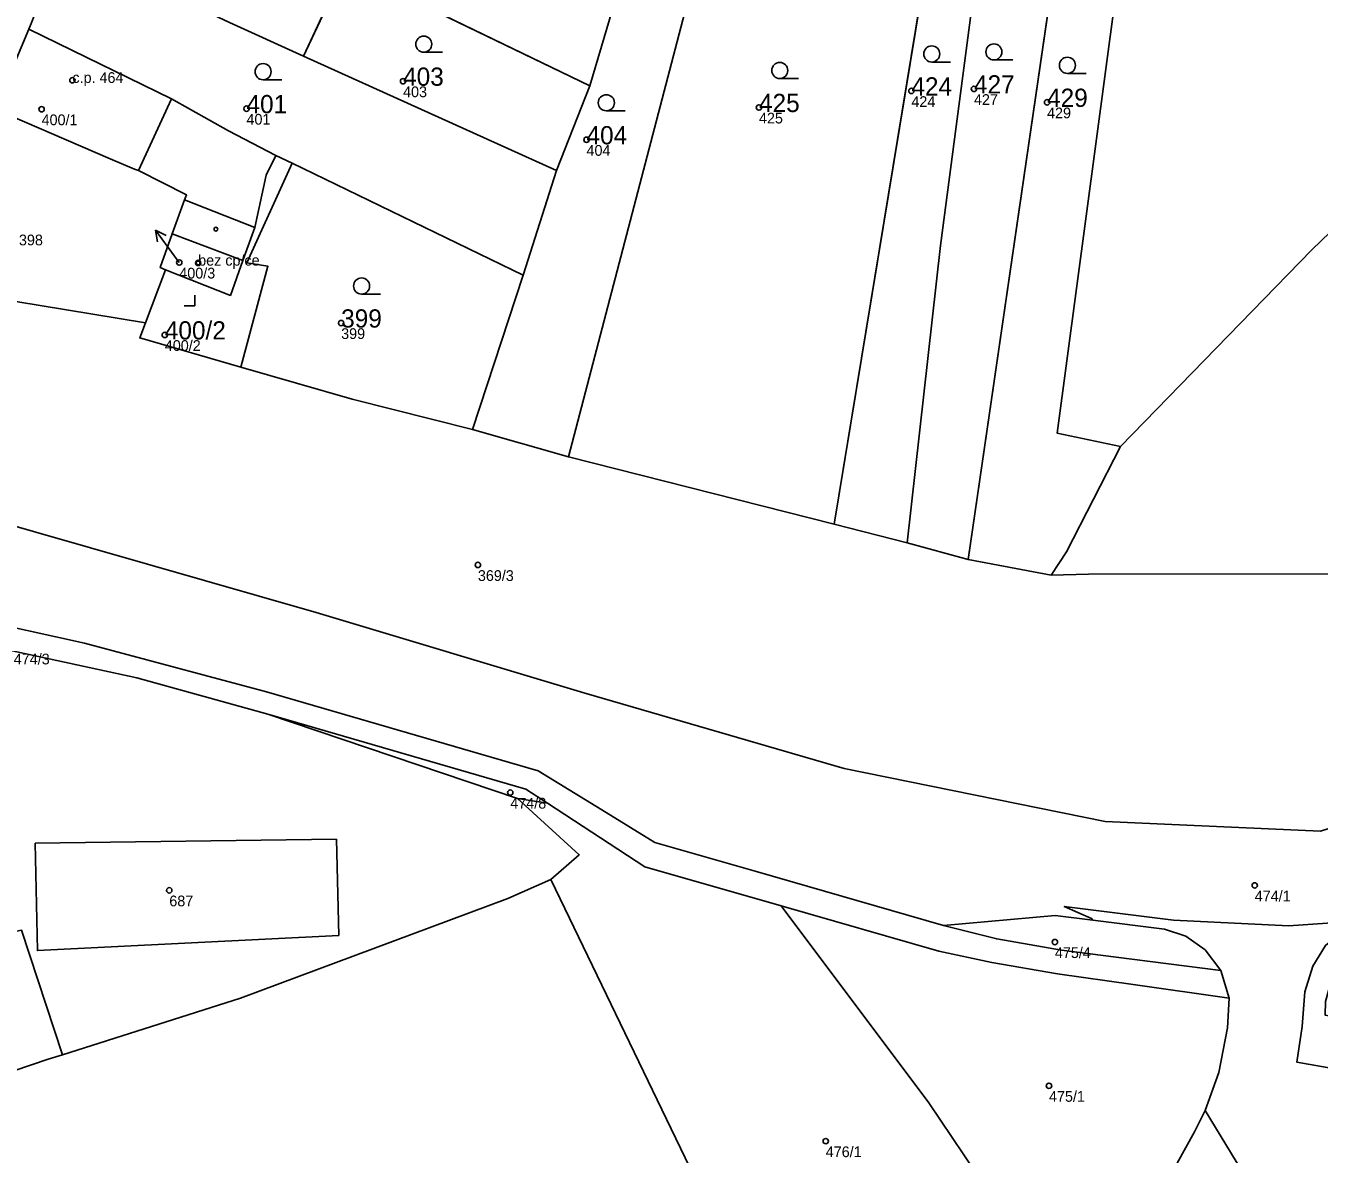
# Model space of a CAD drawing. Extents: x -878211 to -870363, y -1058464 to -1052522.
# Drawn here: x -874484.1 to -874363.6, y -1056425.6 to -1056320.4 of the extents above; entities that cross this region are included whole.
import ezdxf

# ---------------------------------------------------------------- set-up
doc = ezdxf.new("R2010")
doc.units = 0
for name, color, linetype in [('Vrstva 1', 7, 'Continuous'), ('Vrstva 2', 7, 'Continuous'), ('Vrstva 3', 7, 'Continuous'), ('Vrstva 4', 7, 'Continuous'), ('Vrstva 5', 7, 'Continuous'), ('Vrstva 50', 7, 'Continuous'), ('Vrstva 51', 7, 'Continuous'), ('Vrstva 52', 7, 'Continuous'), ('Vrstva 7', 7, 'Continuous')]:
    doc.layers.add(name, color=color, linetype=linetype)

msp = doc.modelspace()

# ---------------------------------------------------------------- linework, layer by layer
at = {"layer": 'Vrstva 1'}
for p, q in [((-874394.05, -1056277.02), (-874408.81, -1056366.88)), ((-874396.34, -1056370.15), (-874384.87, -1056291.52)), ((-874458.27, -1056323.23), (-874454.4, -1056314.98)), ((-874431.59, -1056326), (-874454.4, -1056314.98)), ((-874434.69, -1056333.9), (-874458.27, -1056323.23)), ((-874434.69, -1056333.9), (-874431.59, -1056326)), ((-874459.33, -1056333.22), (-874460.83, -1056332.49)), ((-874437.8, -1056343.65), (-874459.33, -1056333.22)), ((-874437.8, -1056343.65), (-874434.69, -1056333.9)), ((-874470.49, -1056339.81), (-874463.91, -1056342.3)), ((-874473, -1056348.11), (-874471.14, -1056343.15)), ((-874442.52, -1056358.05), (-874437.8, -1056343.65)), ((-874473.53, -1056349.51), (-874464.1, -1056352.23)), ((-874464.1, -1056352.23), (-874453.72, -1056355.22)), ((-874453.72, -1056355.22), (-874442.52, -1056358.05)), ((-874433.58, -1056360.58), (-874442.52, -1056358.05)), ((-874433.58, -1056360.58), (-874408.81, -1056366.88))]:
    msp.add_line(p, q, dxfattribs=at)
for points in [[(-874417.27, -1056285.77), (-874419.76, -1056303.99), (-874420.48, -1056308.81), (-874422.58, -1056318.54), (-874433.58, -1056360.58)], [(-874402.03, -1056368.61), (-874398.91, -1056340.89), (-874395.91, -1056317.97), (-874390.55, -1056288.09)], [(-874382.15, -1056359.62), (-874388.04, -1056358.4), (-874382.65, -1056317.89), (-874379.48, -1056292.14)], [(-874428.05, -1056309.75), (-874428.16, -1056314.44), (-874431.59, -1056326)], [(-874388.61, -1056371.61), (-874385.14, -1056371.54), (-874356.24, -1056371.49), (-874347.06, -1056367.91), (-874344.01, -1056366.72), (-874341.65, -1056364.53), (-874305.59, -1056328.15), (-874284.45, -1056312)], [(-874458.27, -1056323.23), (-874465.16, -1056320.12), (-874480.74, -1056312.73)], [(-874460.83, -1056332.49), (-874465.27, -1056330.21), (-874470.58, -1056327.23), (-874483.86, -1056320.72)], [(-874470.49, -1056339.81), (-874469.35, -1056336.63), (-874469.17, -1056336.17), (-874473.64, -1056333.91), (-874474.02, -1056333.77), (-874476.28, -1056332.82), (-874487.02, -1056328.19)], [(-874348.41, -1056328.4), (-874349.53, -1056329.25), (-874357.55, -1056334.76), (-874364.33, -1056341.31), (-874382.15, -1056359.62)], [(-874460.83, -1056332.49), (-874461.75, -1056334.33), (-874462.81, -1056339.21), (-874463.91, -1056342.3)], [(-874459.33, -1056333.22), (-874463.54, -1056342.5), (-874461.59, -1056342.82), (-874464.1, -1056352.23)], [(-874471.14, -1056343.15), (-874471.62, -1056342.95), (-874470.49, -1056339.81)], [(-874463.91, -1056342.3), (-874465.07, -1056345.54), (-874471.14, -1056343.15)], [(-874388.61, -1056371.61), (-874387.19, -1056369.44), (-874382.15, -1056359.62)]]:
    msp.add_lwpolyline(points, dxfattribs=at)
at = {"layer": 'Vrstva 3'}
for p, q in [((-874447.063, -1056322.88), (-874445.313, -1056322.88)), ((-874399.733, -1056323.79), (-874397.983, -1056323.79)), ((-874393.943, -1056323.6), (-874392.193, -1056323.6)), ((-874462.033, -1056325.44), (-874460.283, -1056325.44)), ((-874413.893, -1056325.33), (-874412.143, -1056325.33)), ((-874387.093, -1056324.85), (-874385.343, -1056324.85)), ((-874430.053, -1056328.34), (-874428.303, -1056328.34)), ((-874468.4, -1056346.52), (-874468.4, -1056345.52)), ((-874452.853, -1056345.42), (-874451.103, -1056345.42)), ((-874469.401, -1056346.52), (-874468.4, -1056346.52))]:
    msp.add_line(p, q, dxfattribs=at)
for centre in [(-874447.06286, -1056322.12981), (-874399.73286, -1056323.03981), (-874393.94286, -1056322.84981), (-874462.03286, -1056324.68981), (-874413.89286, -1056324.57981), (-874387.09286, -1056324.09981), (-874430.05286, -1056327.58981), (-874452.85286, -1056344.66981)]:
    msp.add_circle(centre, 0.75, dxfattribs=at)
at = {"layer": 'Vrstva 4'}
for p, q in [((-874473.64, -1056333.91), (-874470.58, -1056327.23)), ((-874469.35, -1056336.63), (-874462.81, -1056339.21))]:
    msp.add_line(p, q, dxfattribs=at)
at = {"layer": 'Vrstva 5'}
for centre in [(-874466.4268, -1056339.36916), (-874468.0868, -1056342.51916)]:
    msp.add_circle(centre, 0.175, dxfattribs=at)
at = {"layer": 'Vrstva 50'}
for centre in [(-874479.8, -1056325.48994), (-874448.99, -1056325.57994), (-874401.63, -1056326.48994), (-874395.8, -1056326.29994), (-874415.83, -1056328.02994), (-874388.99, -1056327.54994), (-874482.67, -1056328.18994), (-874463.58, -1056328.13994), (-874431.9, -1056331.03994), (-874469.84, -1056342.47994), (-874468.08, -1056342.51994), (-874454.76, -1056348.11994), (-874471.19, -1056349.22994), (-874442.02, -1056370.66994), (-874439, -1056391.88994), (-874470.77, -1056400.99994), (-874369.64, -1056400.53994), (-874388.26, -1056405.81994), (-874388.81, -1056419.21994), (-874409.61, -1056424.37994)]:
    msp.add_circle(centre, 0.25, dxfattribs=at)
at = {"layer": 'Vrstva 51'}
for points in [[(-874408.81, -1056366.88), (-874394.05, -1056277.02), (-874401.74, -1056275.56), (-874403.83, -1056275.64), (-874403.83, -1056277.39), (-874403.02, -1056283.55), (-874406.67, -1056284.12), (-874410.17, -1056284.66), (-874413.67, -1056285.21), (-874416.82, -1056285.7), (-874417.27, -1056285.77), (-874419.76, -1056303.99), (-874420.48, -1056308.81), (-874422.58, -1056318.54), (-874433.58, -1056360.58)], [(-874402.03, -1056368.61), (-874398.91, -1056340.89), (-874395.91, -1056317.97), (-874390.55, -1056288.09), (-874389.52, -1056277.88), (-874394.05, -1056277.02), (-874408.81, -1056366.88)], [(-874396.34, -1056370.15), (-874384.87, -1056291.52), (-874382.69, -1056279.17), (-874389.52, -1056277.88), (-874390.55, -1056288.09), (-874395.91, -1056317.97), (-874398.91, -1056340.89), (-874402.03, -1056368.61)], [(-874388.61, -1056371.61), (-874387.19, -1056369.44), (-874382.15, -1056359.62), (-874388.04, -1056358.4), (-874382.65, -1056317.89), (-874379.48, -1056292.14), (-874378.04, -1056280.05), (-874382.69, -1056279.17), (-874384.87, -1056291.52), (-874396.34, -1056370.15)], [(-874428.05, -1056309.75), (-874428.16, -1056314.44), (-874431.59, -1056326), (-874434.69, -1056333.9), (-874437.8, -1056343.65), (-874442.52, -1056358.05), (-874433.58, -1056360.58), (-874422.58, -1056318.54), (-874420.48, -1056308.81), (-874419.76, -1056303.99), (-874417.27, -1056285.77), (-874420.36, -1056286.3), (-874424.05, -1056286.92), (-874427.89, -1056287.57), (-874431.19, -1056288.13), (-874432.46, -1056288.35), (-874430.92, -1056292.23), (-874429.1, -1056294.96), (-874425.54, -1056295.23), (-874426.84, -1056310.1)], [(-874428.05, -1056309.75), (-874445.92, -1056303.86), (-874449.03, -1056302.71), (-874453.23, -1056312.49), (-874454.4, -1056314.98), (-874431.59, -1056326), (-874428.16, -1056314.44)], [(-874462.69, -1056311.5), (-874462.85, -1056311.43), (-874476.21, -1056304.64), (-874480.74, -1056312.73), (-874465.16, -1056320.12), (-874458.27, -1056323.23), (-874454.4, -1056314.98), (-874460.07, -1056312.6)], [(-874305.59, -1056328.15), (-874284.45, -1056312), (-874285.09, -1056309.2), (-874306.98, -1056315.64), (-874311.81, -1056317.09), (-874332.51, -1056323.25), (-874331.57, -1056326.4), (-874336.9, -1056327.87), (-874347.73, -1056330.86), (-874348.41, -1056328.4), (-874349.53, -1056329.25), (-874357.55, -1056334.76), (-874364.33, -1056341.31), (-874382.15, -1056359.62), (-874387.19, -1056369.44), (-874388.61, -1056371.61), (-874385.14, -1056371.54), (-874356.24, -1056371.49), (-874347.06, -1056367.91), (-874344.01, -1056366.72), (-874341.65, -1056364.53)], [(-874434.69, -1056333.9), (-874458.27, -1056323.23), (-874465.16, -1056320.12), (-874480.74, -1056312.73), (-874483.57, -1056320.05), (-874483.86, -1056320.72), (-874470.58, -1056327.23), (-874465.27, -1056330.21), (-874460.83, -1056332.49), (-874459.33, -1056333.22), (-874437.8, -1056343.65)], [(-874431.59, -1056326), (-874454.4, -1056314.98), (-874458.27, -1056323.23), (-874434.69, -1056333.9)], [(-874470.49, -1056339.81), (-874463.91, -1056342.3), (-874462.81, -1056339.21), (-874461.75, -1056334.33), (-874460.83, -1056332.49), (-874465.27, -1056330.21), (-874470.58, -1056327.23), (-874483.86, -1056320.72), (-874486.75, -1056327.55), (-874487.02, -1056328.19), (-874476.28, -1056332.82), (-874474.02, -1056333.77), (-874473.64, -1056333.91), (-874469.17, -1056336.17), (-874469.35, -1056336.63)], [(-874473, -1056348.11), (-874471.14, -1056343.15), (-874471.62, -1056342.95), (-874470.49, -1056339.81), (-874469.35, -1056336.63), (-874469.17, -1056336.17), (-874473.64, -1056333.91), (-874474.02, -1056333.77), (-874476.28, -1056332.82), (-874487.02, -1056328.19), (-874487.42, -1056329.42), (-874492.46, -1056344.89)], [(-874464.1, -1056352.23), (-874461.59, -1056342.82), (-874463.54, -1056342.5), (-874459.33, -1056333.22), (-874460.83, -1056332.49), (-874461.75, -1056334.33), (-874462.81, -1056339.21), (-874463.91, -1056342.3), (-874465.07, -1056345.54), (-874471.14, -1056343.15), (-874473, -1056348.11), (-874473.53, -1056349.51)], [(-874453.72, -1056355.22), (-874442.52, -1056358.05), (-874437.8, -1056343.65), (-874459.33, -1056333.22), (-874463.54, -1056342.5), (-874461.59, -1056342.82), (-874464.1, -1056352.23)], [(-874471.14, -1056343.15), (-874465.07, -1056345.54), (-874463.91, -1056342.3), (-874470.49, -1056339.81), (-874471.62, -1056342.95)], [(-874480.73, -1056416.32), (-874464.13, -1056411.06), (-874439.22, -1056401.77), (-874435.23, -1056399.98), (-874432.58, -1056397.69), (-874438.32, -1056392.45), (-874461.59, -1056384.57), (-874473.8, -1056381.18), (-874495.04, -1056376.59), (-874496.42, -1056387.17), (-874497.18, -1056388.52), (-874500.89, -1056392.21), (-874504.25, -1056392.93), (-874510.08, -1056393.87), (-874552.37, -1056396.35), (-874577.98, -1056401.51), (-874580.53, -1056402.03), (-874578.38, -1056409.61), (-874573.13, -1056410.85), (-874572.76, -1056413.05), (-874571.8, -1056418.71), (-874544.06, -1056414.29), (-874506.28, -1056409.52), (-874484.53, -1056404.72)], [(-874438.32, -1056392.45), (-874435.53, -1056392.89), (-874437.55, -1056391.57), (-874461.59, -1056384.57)], [(-874361.01, -1056406.98), (-874359.27, -1056405.94), (-874352.93, -1056404.59), (-874347.41, -1056403.07), (-874318.59, -1056393.97), (-874317.8, -1056395.68), (-874314.94, -1056394.5), (-874315.68, -1056390.9), (-874347.93, -1056401.08), (-874353.93, -1056402.7), (-874359.31, -1056403.8), (-874360.99, -1056404.48), (-874363.04, -1056406.14), (-874364.23, -1056408.07), (-874364.97, -1056410.45), (-874365.23, -1056413.7), (-874365.71, -1056417.03), (-874353.17, -1056419.23), (-874351.21, -1056414.7), (-874363.09, -1056412.62), (-874363.04, -1056411.36), (-874362.3, -1056408.69)], [(-874455.2, -1056396.23), (-874454.98, -1056405.2), (-874483.06, -1056406.62), (-874483.26, -1056396.61)], [(-874455.2, -1056396.23), (-874483.26, -1056396.61), (-874483.06, -1056406.62), (-874454.98, -1056405.2)], [(-874480.73, -1056416.32), (-874482.07, -1056416.75), (-874490.03, -1056419.45), (-874505.5, -1056424.13), (-874506.63, -1056424.46), (-874506.09, -1056462.44), (-874483.53, -1056458.93), (-874476.75, -1056456.82), (-874458.26, -1056450.98), (-874448.21, -1056442.41), (-874441.44, -1056436.86), (-874425.29, -1056433.14), (-874420.12, -1056431.27), (-874435.23, -1056399.98), (-874439.22, -1056401.77), (-874464.13, -1056411.06)], [(-874413.76, -1056402.45), (-874399.99, -1056420.8), (-874384.79, -1056443.42), (-874382.93, -1056444.85), (-874382.6, -1056441.37), (-874382, -1056437.94), (-874381.27, -1056435.06), (-874380.43, -1056433.22), (-874379.13, -1056430.54), (-874375.26, -1056423.52), (-874374.27, -1056421.51), (-874373, -1056417.98), (-874372.17, -1056413.82), (-874372.03, -1056411.06), (-874380.96, -1056409.78), (-874388.01, -1056408.78), (-874394.12, -1056407.72), (-874399.07, -1056406.68)], [(-874372.79, -1056408.47), (-874374.26, -1056406.56), (-874376.05, -1056405.28), (-874378.06, -1056404.61), (-874384.74, -1056403.78), (-874388.24, -1056403.34), (-874398.64, -1056404.27), (-874393.67, -1056405.53), (-874387.64, -1056406.59), (-874382.56, -1056407.24)], [(-874506.63, -1056424.46), (-874505.5, -1056424.13), (-874490.03, -1056419.45), (-874482.07, -1056416.75), (-874480.73, -1056416.32), (-874484.53, -1056404.72), (-874506.28, -1056409.52), (-874544.06, -1056414.29), (-874571.8, -1056418.71), (-874569.39, -1056432.89), (-874561.56, -1056432.43), (-874554.89, -1056431.78), (-874547.93, -1056431.29), (-874538.64, -1056430.41), (-874535.46, -1056430.33), (-874523.03, -1056429.03), (-874509.91, -1056425.43)]]:
    msp.add_lwpolyline(points, close=True, dxfattribs=at)
for points in [[(-874486.75, -1056327.55), (-874483.86, -1056320.72), (-874483.57, -1056320.05), (-874480.74, -1056312.73), (-874476.21, -1056304.64), (-874473.19, -1056299.28), (-874471.52, -1056296.81), (-874469.69, -1056293.7), (-874480.72, -1056293.66), (-874486.23, -1056307.5)], [(-874284.45, -1056312), (-874305.59, -1056328.15), (-874341.65, -1056364.53), (-874344.01, -1056366.72), (-874347.06, -1056367.91), (-874356.24, -1056371.49), (-874385.14, -1056371.54), (-874388.61, -1056371.61), (-874396.34, -1056370.15), (-874402.03, -1056368.61), (-874408.81, -1056366.88), (-874433.58, -1056360.58), (-874442.52, -1056358.05), (-874453.72, -1056355.22), (-874464.1, -1056352.23), (-874473.53, -1056349.51), (-874473, -1056348.11), (-874492.46, -1056344.89)], [(-874382.65, -1056317.89), (-874388.04, -1056358.4), (-874382.15, -1056359.62), (-874364.33, -1056341.31), (-874357.55, -1056334.76), (-874349.53, -1056329.25), (-874348.41, -1056328.4), (-874337.74, -1056324.81), (-874332.51, -1056323.25), (-874311.81, -1056317.09)], [(-874488.56, -1056366.09), (-874457.08, -1056375.11), (-874432.15, -1056382.58), (-874407.9, -1056389.64), (-874383.57, -1056394.58), (-874363.5, -1056395.5), (-874329.41, -1056384.68), (-874311.2, -1056368.22), (-874284.49, -1056339.46), (-874263.34, -1056326.47), (-874262.52, -1056328.77), (-874260.4, -1056327.93), (-874261.1, -1056326.28), (-874247.93, -1056324.46), (-874211.49, -1056322.17)], [(-874205.44, -1056365.67), (-874230.66, -1056368.26), (-874238.99, -1056368.29), (-874258.43, -1056369.19), (-874280.88, -1056373.67), (-874329.41, -1056384.68), (-874363.5, -1056395.5), (-874383.57, -1056394.58), (-874407.9, -1056389.64), (-874432.15, -1056382.58), (-874457.08, -1056375.11), (-874488.56, -1056366.09)], [(-874495.04, -1056376.59), (-874473.8, -1056381.18), (-874461.59, -1056384.57), (-874437.55, -1056391.57), (-874435.53, -1056392.89), (-874426.47, -1056398.8), (-874413.76, -1056402.45), (-874399.07, -1056406.68), (-874394.12, -1056407.72), (-874388.01, -1056408.78), (-874380.96, -1056409.78), (-874372.03, -1056411.06), (-874372.79, -1056408.47), (-874382.56, -1056407.24), (-874387.64, -1056406.59), (-874393.67, -1056405.53), (-874398.64, -1056404.27), (-874416.2, -1056399.21), (-874425.52, -1056396.53), (-874430.06, -1056393.75), (-874436.39, -1056389.87), (-874461.71, -1056382.51), (-874478.68, -1056377.96), (-874492.07, -1056375.02)], [(-874492.07, -1056375.02), (-874478.68, -1056377.96), (-874461.71, -1056382.51), (-874436.39, -1056389.87), (-874430.06, -1056393.75), (-874425.52, -1056396.53), (-874416.2, -1056399.21), (-874398.64, -1056404.27), (-874388.24, -1056403.34), (-874384.74, -1056403.78), (-874384.84, -1056403.62), (-874387.39, -1056402.52), (-874377.2, -1056403.78), (-874366.46, -1056404.32), (-874359.31, -1056403.8)], [(-874384.79, -1056443.42), (-874399.99, -1056420.8), (-874413.76, -1056402.45), (-874426.47, -1056398.8), (-874435.53, -1056392.89), (-874438.32, -1056392.45), (-874432.58, -1056397.69), (-874435.23, -1056399.98), (-874420.12, -1056431.27)], [(-874358.83, -1056429.38), (-874355.4, -1056424.52), (-874353.17, -1056419.23), (-874365.71, -1056417.03), (-874365.23, -1056413.7), (-874364.97, -1056410.45), (-874364.23, -1056408.07), (-874363.04, -1056406.14), (-874360.99, -1056404.48), (-874359.31, -1056403.8), (-874366.46, -1056404.32), (-874377.2, -1056403.78), (-874387.39, -1056402.52), (-874384.84, -1056403.62), (-874384.74, -1056403.78), (-874378.06, -1056404.61), (-874376.05, -1056405.28), (-874374.26, -1056406.56), (-874372.79, -1056408.47), (-874372.03, -1056411.06), (-874372.17, -1056413.82), (-874373, -1056417.98), (-874374.27, -1056421.51), (-874364.19, -1056438.09)], [(-874364.19, -1056438.09), (-874374.27, -1056421.51), (-874375.26, -1056423.52), (-874379.13, -1056430.54)]]:
    msp.add_lwpolyline(points, dxfattribs=at)
at = {"layer": 'Vrstva 52'}
for points in [[(-874483.86, -1056320.72), (-874486.75, -1056327.55), (-874487.02, -1056328.19), (-874476.28, -1056332.82), (-874474.02, -1056333.77), (-874473.64, -1056333.91), (-874470.58, -1056327.23)], [(-874465.07, -1056345.54), (-874463.91, -1056342.3), (-874470.49, -1056339.81), (-874471.62, -1056342.95), (-874471.14, -1056343.15)]]:
    msp.add_lwpolyline(points, close=True, dxfattribs=at)
at = {"layer": 'Vrstva 7'}
for p, q in [((-874470.28, -1056341.88), (-874472.044, -1056339.452)), ((-874472.044, -1056339.452), (-874471.05, -1056339.968)), ((-874472.044, -1056339.452), (-874471.86, -1056340.557)), ((-874469.84, -1056342.48), (-874470.28, -1056341.88))]:
    msp.add_line(p, q, dxfattribs=at)

# ---------------------------------------------------------------- texts
at = {"layer": 'Vrstva 2'}
for s, p in [('403', (-874448.99, -1056326.005)), ('424', (-874401.63, -1056326.915)), ('427', (-874395.8, -1056326.725)), ('429', (-874388.99, -1056327.975)), ('401', (-874463.58, -1056328.564)), ('425', (-874415.83, -1056328.455)), ('404', (-874431.9, -1056331.465)), ('399', (-874454.76, -1056348.545)), ('400/2', (-874471.19, -1056349.655))]:
    msp.add_text(s, height=1.699998, dxfattribs=at).set_placement(p)
at = {"layer": 'Vrstva 50'}
for s, p in [('c.p. 464', (-874479.8, -1056325.74)), ('403', (-874448.99, -1056327.069)), ('424', (-874401.63, -1056327.979)), ('427', (-874395.8, -1056327.789)), ('400/1', (-874482.67, -1056329.679)), ('401', (-874463.58, -1056329.629)), ('425', (-874415.83, -1056329.519)), ('429', (-874388.99, -1056329.039)), ('404', (-874431.9, -1056332.529)), ('398', (-874484.78, -1056340.879)), ('bez cp/ce', (-874468.08, -1056342.77)), ('400/3', (-874469.84, -1056343.969)), ('399', (-874454.76, -1056349.609)), ('400/2', (-874471.19, -1056350.719)), ('369/3', (-874442.02, -1056372.159)), ('474/3', (-874485.26, -1056379.939)), ('474/8', (-874439, -1056393.379)), ('474/1', (-874369.64, -1056402.029)), ('687', (-874470.77, -1056402.489)), ('475/4', (-874388.26, -1056407.309)), ('475/1', (-874388.81, -1056420.709)), ('476/1', (-874409.61, -1056425.869))]:
    msp.add_text(s, height=0.999996, dxfattribs=at).set_placement(p)

doc.saveas('drawing.dxf')
